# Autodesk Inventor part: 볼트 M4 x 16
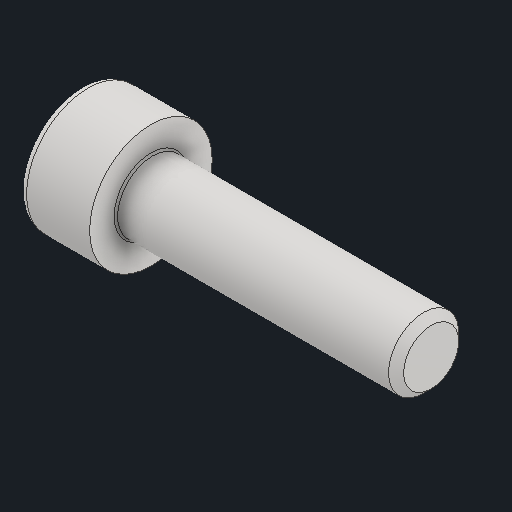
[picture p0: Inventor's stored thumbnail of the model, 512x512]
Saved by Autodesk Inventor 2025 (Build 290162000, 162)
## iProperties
Created: 2025-08
Part Number: 볼트 M4 x 16
Material: 스테인리스강
Description: 6각 소켓 머리 캡 나사
Document SubType Name: Modeling
Designer: infra14
Density: 8.08 g/cm^3
Appearance: 기본값
Author: jhkim
Sending System: Autodesk Inventor 2026
Preprocessor: ST-DEVELOPER v20.1
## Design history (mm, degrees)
feature "Solid1"
node "솔리드1"
